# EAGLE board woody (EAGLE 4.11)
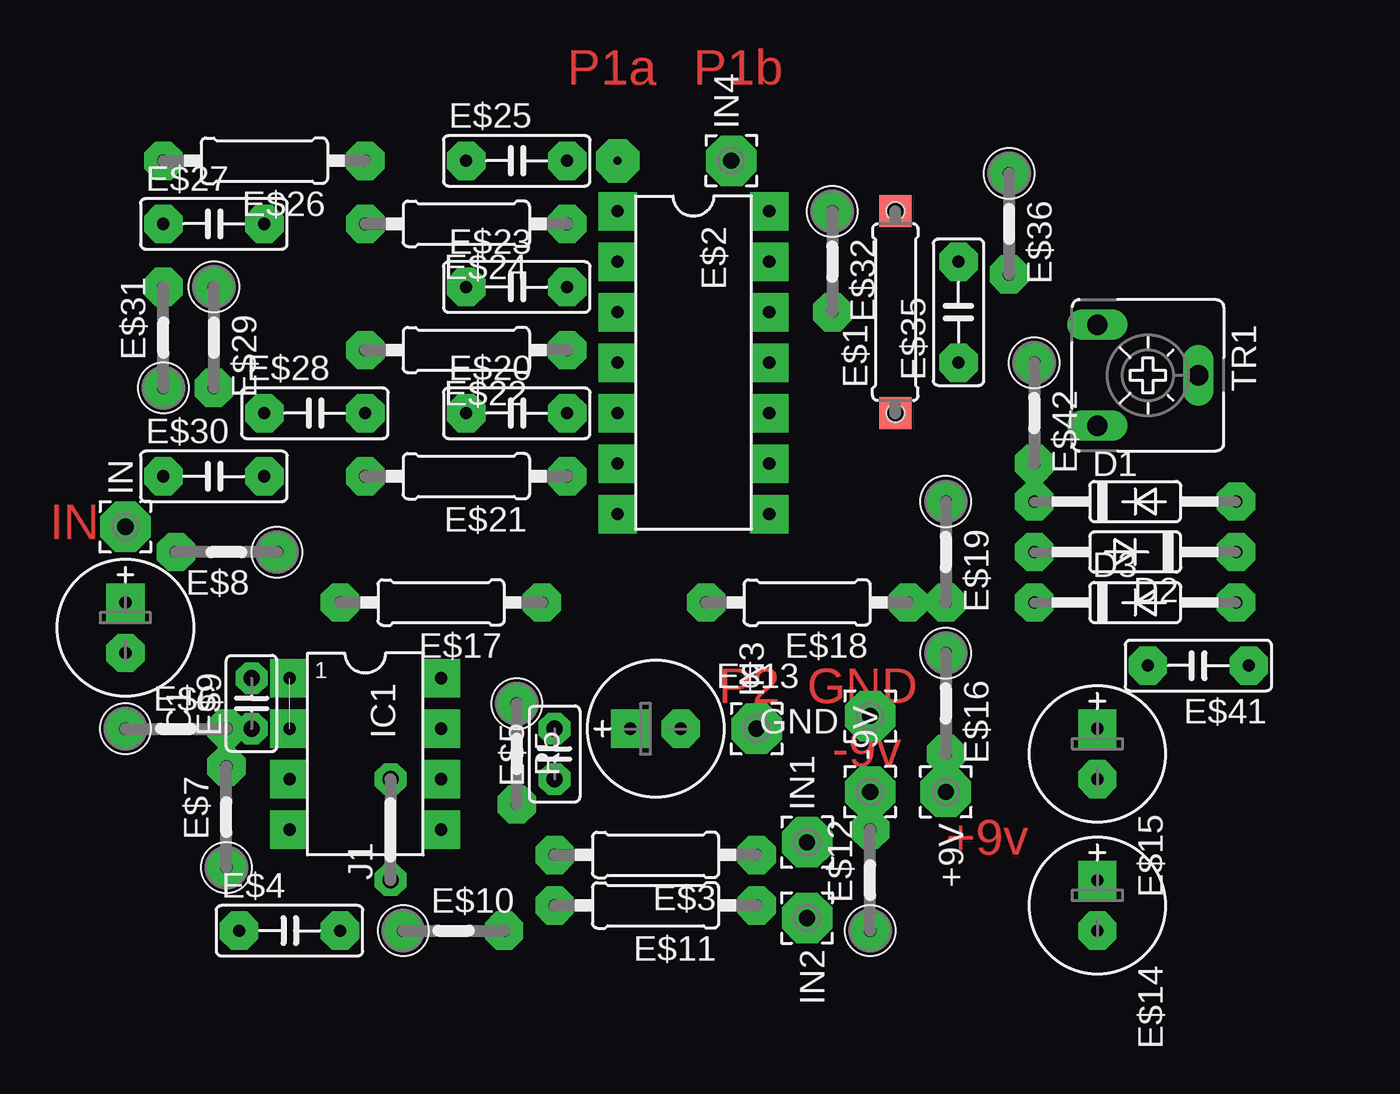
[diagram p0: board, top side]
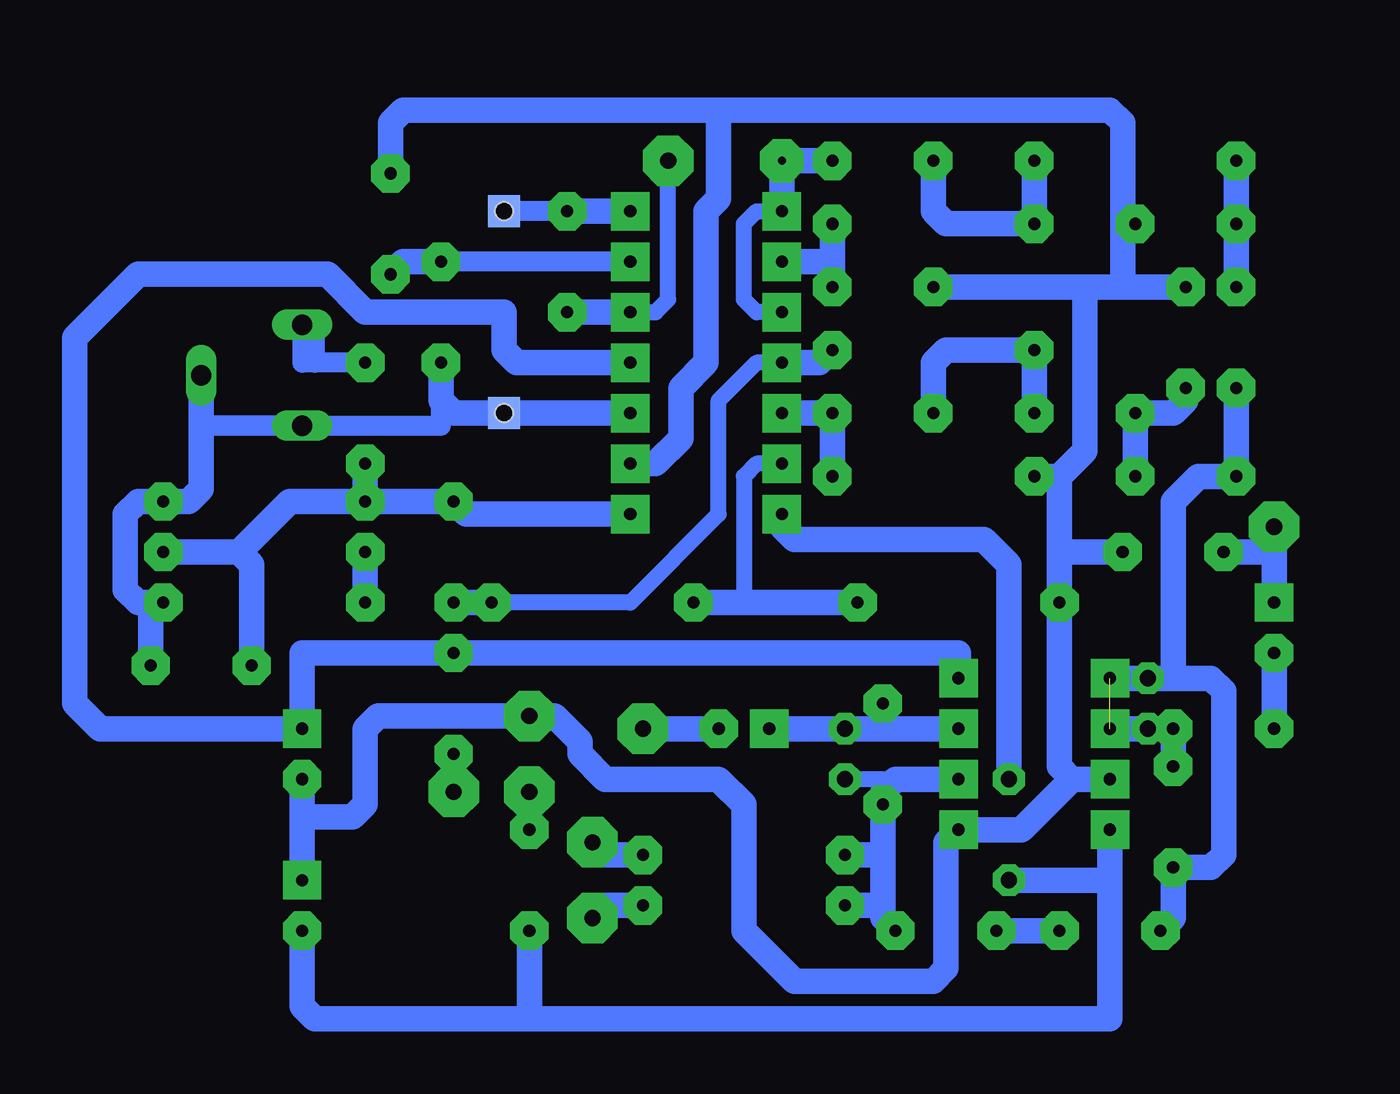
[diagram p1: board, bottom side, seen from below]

No outline drawn. Coordinates in mm, seen from the top.
Copper layers (1*16): Top 0.035mm / dielectric 1.5mm / Bottom 0.035mm
Design rules "default": minimum track width 10mil, minimum drill 24mil, track to track 8mil, track to pad 8mil, pad to pad 8mil, via to via 8mil, smd to smd 8mil, copper to edge 40mil, drill to drill 8mil, minimum pad ring 10mil, minimum via ring 8mil, stop-mask expansion 4mil, vias tented up to drill 0mil, thermal gap 10mil

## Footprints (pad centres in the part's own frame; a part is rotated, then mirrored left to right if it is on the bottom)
2,54/0,8 = drill 0.813 pad 2.54 octagon: 1 0,0
E2,5-7 = drill 0.61 pad 1.93 square: + -1.27,0 | drill 0.61 pad 1.93 octagon: - 1.27,0
DO35-10 = drill 0.61 pad 1.93 octagon: A 5.08,0; C -5.08,0
R4207/10 = smd 1.6 x 1.6: A1 -5.08,0; A2 5.08,0 | smd 1.6 x 1.6 bottom: B1 -5.08,0; B2 5.08,0 | hole 0.9: -5.08,0; 5.08,0
DIL14 = drill 0.61 pad 1.93 square: 1 -7.62,-3.81; 2 -5.08,-3.81; 3 -2.54,-3.81; 4 0,-3.81; 5 2.54,-3.81; 6 5.08,-3.81; 7 7.62,-3.81; 8 7.62,3.81; 9 5.08,3.81; 10 2.54,3.81; 11 0,3.81; 12 -2.54,3.81; 13 -5.08,3.81; 14 -7.62,3.81
0207/10 = drill 0.61 pad 1.93 octagon: 1 -5.08,0; 2 5.08,0
C050-025X075 = drill 0.61 pad 1.93 octagon: 1 -2.54,0; 2 2.54,0
C2.5-2 = drill 0.813 pad 1.6 octagon: 1 -1.27,0; 2 1.27,0
0207/5V = drill 0.61 pad 1.93 octagon: 1 -2.54,0; 2 2.54,0
DIL08 = drill 0.61 pad 1.93 square: 1 -3.81,-3.81; 2 -1.27,-3.81; 3 1.27,-3.81; 4 3.81,-3.81; 5 3.81,3.81; 6 1.27,3.81; 7 -1.27,3.81; 8 -3.81,3.81
05 = drill 0.813 pad 1.6 octagon: 1 -2.54,0; 2 2.54,0
CA6V = drill 1.016 long: A -2.54,-2.54; E 2.54,-2.54; S 0,2.54

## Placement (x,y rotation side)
+9V  [2,54/0,8]  48.9,17.14 180 top
-9V  [2,54/0,8]  45.09,17.14 0 top
C1  1uf  [E2,5-7]  7.62,25.4 270 top
D1  1N4148  [DO35-10]  58.42,31.75 0 top
D2  1N4148  [DO35-10]  58.42,29.21 180 top
D3  1N4148  [DO35-10]  58.42,26.67 0 top
E$1  10K  [R4207/10]  46.35,41.27 90 top
E$2  LM4136  [DIL14]  36.2,38.73 270 top
E$3  3K3  [0207/10]  34.29,13.97 180 top
E$4  39nf  [C050-025X075]  15.88,10.16 0 top
E$5  small pf cap  [C2.5-2]  29.21,19.05 90 top
E$6  10K  [0207/5V]  10.16,20.32 0 top
E$7  12K  [0207/5V]  12.7,15.88 90 top
E$8  1M  [0207/5V]  12.7,29.21 180 top
E$9  small pf cap  [C2.5-2]  13.97,21.59 90 top
E$10  12K  [0207/5V]  24.13,10.16 0 top
E$11  12K  [0207/10]  34.29,11.43 180 top
E$12  100  [0207/5V]  45.09,12.7 90 top
E$13  10uf  [E2,5-7]  34.29,20.32 0 top
E$14  47uf  [E2,5-7]  56.52,11.43 270 top
E$15  47uf  [E2,5-7]  56.52,19.05 270 top
E$16  100  [0207/5V]  48.9,21.59 270 top
E$17  22K  [0207/10]  23.5,26.67 180 top
E$18  22K  [0207/10]  41.91,26.67 180 top
E$19  10K  [0207/5V]  48.9,29.21 270 top
E$20  3n3  [C050-025X075]  27.3,36.2 0 top
E$21  10K  [0207/10]  24.77,33.02 180 top
E$22  10K  [0207/10]  24.77,39.37 180 top
E$23  39nf  [C050-025X075]  27.3,42.55 0 top
E$24  10K  [0207/10]  24.77,45.72 180 top
E$25  39nf  [C050-025X075]  27.3,48.9 0 top
E$26  10K  [0207/10]  14.61,48.9 180 top
E$27  39nf  [C050-025X075]  12.06,45.72 0 top
E$28  3n3  [C050-025X075]  17.14,36.2 0 top
E$29  10k  [0207/5V]  12.06,40.01 270 top
E$30  3n3  [C050-025X075]  12.06,33.02 0 top
E$31  10k  [0207/5V]  9.53,40.01 90 top
E$32  10K  [0207/5V]  43.18,43.81 270 top
E$35  10nf  [C050-025X075]  49.53,41.27 90 top
E$36  100K  [0207/5V]  52.07,45.72 270 top
E$41  100pf  [C050-025X075]  61.59,23.5 180 top
E$42  150K  [0207/5V]  53.34,36.2 270 top
GND  [2,54/0,8]  45.09,20.95 90 top
IC1  TL072  [DIL08]  19.68,19.05 270 top
IN  [2,54/0,8]  7.62,30.48 0 top
IN1  [2,54/0,8]  41.91,14.61 0 top
IN2  [2,54/0,8]  41.91,10.79 180 top
IN3  OUT  [2,54/0,8]  39.37,20.32 0 top
IN4  [2,54/0,8]  38.1,48.9 0 top
J1  0K  [05]  20.95,15.24 90 top
R5  22K  [0207/5V]  27.3,19.05 270 top
TR1  500K  [CA6V]  59.05,38.1 270 top

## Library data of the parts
+9V -9V GND IN IN1-IN4 = wirepad
C1 E$3 E$4 E$6-E$8 E$10-E$32 E$35 E$36 E$41 E$42 R5 = rcl
D1-D3 = diode
E$1 = resistor-ruf
E$2 IC1 = ic-package
E$5 E$9 = capacitor-wima
J1 = jumper
TR1 = pot

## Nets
IC2: E$2.9 E$8.1 E$14.+ E$15.- E$17.2 E$21.2 E$23.1 E$27.2 E$29.1 E$36.1 GND.1 IC1.3 IC1.5
R2: E$4.1 E$6.2 E$7.1 E$7.2 E$30.1 E$31.1 IC1.1 IC1.2
S$1: C1.+ E$8.2 IN.1
S$2: C1.- E$6.1
S$4: D1.A D3.A E$2.10 E$35.1 E$41.1 TR1.E TR1.S
S$5: E$13.- IN3.1
S$6: E$11.1 IN2.1
S$7: E$2.7 J1.2
S$8: E$3.2 E$10.2 E$11.2 IC1.6 R5.2
S$9: E$13.+ IC1.7 R5.1
S$10: E$4.2 E$10.1
S$11: E$3.1 IN1.1
S$12: -9V.1 E$12.2
S$13: E$2.11 E$15.+ E$16.1 IC1.8
S$14: E$2.6 E$17.1 E$18.2
S$15: +9V.1 E$16.2
S$16: E$42.1 TR1.A
S$17: E$2.4 E$18.1 E$19.2 E$22.1
S$18: E$5.1
S$20: E$2.5 E$20.2 E$21.1
S$21: E$20.1 E$22.2 E$28.2
S$22: E$2.2 E$23.2 E$24.1
S$23: E$2.1 E$2.3 E$25.2
S$24: E$24.2 E$25.1 E$26.1
S$25: E$26.2 E$27.1 E$31.2
S$26: E$28.1 E$29.2 E$30.2
S$32: E$2.12 E$32.2 IN4.1
S$33: E$1.A2 E$2.14 E$32.1
S$36: E$2.13 E$35.2 E$36.2
S$37: D2.A D3.C
S$38: D1.C D2.C E$2.8 E$19.1 E$41.2 E$42.2
V-: E$12.1 E$14.- IC1.4 J1.1

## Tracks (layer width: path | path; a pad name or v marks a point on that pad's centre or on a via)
IC2
  Bottom 1.27: E$2.9 38.73,33.66 37.47,34.92 37.47,37.47 36.2,38.73 36.2,46.35 35.56,46.99 35.56,51.44 | E$36.1 52.07,50.8 51.44,51.44 35.56,51.44 | 56.52,15.88 E$14.+ | 56.52,15.88 E$15.- | 56.52,15.88 53.98,15.88 53.34,16.51 53.34,20.32 52.7,20.95 GND.1 43.81,20.95 42.55,19.68 42.55,19.05 41.27,17.78 35.56,17.78 34.29,16.51 34.29,10.16 31.75,7.62 24.77,7.62 24.13,8.26 24.13,14.61 IC1.5 20.32,15.24 17.78,17.78 | 35.56,51.44 15.88,51.44 15.24,50.8 15.24,42.55 | E$27.2 15.24,45.72 15.24,42.55 | 15.24,42.55 E$29.1 | 17.14,42.55 E$23.1 | 17.14,42.55 15.24,42.55 | 17.14,42.55 17.14,34.29 18.41,33.02 | 18.41,33.02 E$21.2 | 18.41,29.21 E$8.1 | 18.41,29.21 18.41,33.02 | 18.41,29.21 E$17.2 18.41,18.41 17.78,17.78 | 17.78,17.78 IC1.3
R2  (1 unrouted)
  Bottom 1.27: 12.7,22.86 10.79,22.86 10.16,22.23 10.16,13.97 10.79,13.34 E$7.1 12.7,10.79 E$4.1 | 12.7,22.86 IC1.1 | 12.7,22.86 12.7,31.75 11.43,33.02 E$30.1 E$31.1 | IC1.2 E$6.2 E$7.2
S$1
  Bottom 1.27: IN.1 7.62,29.21 | 7.62,29.21 C1.+ | E$8.2 7.62,29.21
S$2
  Bottom 1.27: C1.- E$6.1
S$3  (via drill 0.41 pad 2.18)
  other vias: 32.38,48.9
S$4
  Bottom 1.016: TR1.E 61.59,35.56 49.53,35.56 49.53,36.83
  Bottom 1.27: TR1.S 61.59,35.56 61.59,32.38 62.23,31.75 D1.A 64.77,31.75 65.41,31.11 65.41,27.3 64.77,26.67 64.14,26.67 | 64.14,26.67 D3.A | E$41.1 64.14,26.67 | E$35.1 49.53,36.83 48.9,36.2 E$2.10
S$5
  Bottom 1.27: E$13.- IN3.1
S$6
  Bottom 1.27: E$11.1 41.27,11.43 | 41.27,11.43 IN2.1 | 41.27,11.43 IN2.1 | 41.27,11.43 IN2.1
S$7
  Bottom 1.27: E$2.7 32.38,30.48 31.75,29.84 22.23,29.84 20.95,28.57 J1.2
S$8
  Bottom 1.27: IC1.6 26.67,17.78 27.3,17.14 R5.2 27.3,13.97 | 27.3,13.97 27.3,11.43 | 27.3,11.43 27.3,10.79 E$10.2 | E$11.2 27.3,11.43 | E$3.2 27.3,13.97
S$9
  Bottom 1.27: IC1.7 27.3,20.32 | 27.3,20.32 R5.1 | 27.3,20.32 E$13.+
S$10
  Bottom 1.27: E$4.2 E$10.1
S$11
  Bottom 1.27: E$3.1 41.27,13.97 | 41.27,13.97 IN1.1 41.27,13.97
S$12
  Bottom 1.27: -9V.1 E$12.2
S$13
  Bottom 1.27: IC1.8 23.5,24.13 E$16.1 56.52,24.13 E$15.+ 66.67,20.32 67.94,21.59 67.94,40.01 64.77,43.18 55.24,43.18 53.34,41.27 46.35,41.27 46.35,39.37 45.72,38.73 E$2.11
S$14
  Bottom 0.813: E$2.6 33.66,33.66 34.29,33.02 34.29,26.67
  Bottom 1.27: E$17.1 34.29,26.67 E$18.2
S$15
  Bottom 1.27: E$16.2 +9V.1
S$16
  Bottom 1.016: E$42.1 55.88,38.73 | 55.88,38.73 56.52,38.73 TR1.A | 55.88,40.64 55.88,38.73
S$17
  Bottom 0.813: E$18.1 40.01,26.67 35.56,31.11 35.56,36.83 33.66,38.73 E$2.4
  Bottom 1.27: E$18.1 E$19.2 | E$2.4 30.48,38.73 E$22.1
S$18
  Bottom 0.813: 27.3,17.78 E$5.1
S$20
  Bottom 1.27: E$2.5 E$20.2 E$21.1
S$21
  Bottom 1.27: E$20.1 24.77,38.73 24.13,39.37 E$22.2 E$28.2
S$22
  Bottom 1.27: E$2.2 29.84,43.81 | E$23.2 29.84,43.81 | 29.84,43.81 E$24.1
S$23
  Bottom 0.813: E$2.3 33.66,41.27 34.29,41.91 34.29,45.72 33.66,46.35 E$2.1
  Bottom 1.27: E$25.2 31.75,48.9 32.38,48.26 E$2.1
S$24
  Bottom 1.27: E$25.1 24.77,46.35 24.13,45.72 E$24.2 E$26.1
S$25
  Bottom 1.27: E$26.2 E$27.1 E$31.2
S$26
  Bottom 1.27: E$29.2 12.06,36.83 12.7,36.2 E$28.1 E$30.2
S$32
  Bottom 0.813: E$2.12 38.73,41.27 38.1,41.91 IN4.1
  Bottom 1.27: E$32.2 E$2.12
S$33
  Bottom 1.016: E$32.1 E$1.A2
  Bottom 1.27: E$2.14 E$32.1
S$36
  Bottom 1.016: E$2.13 E$35.2
  Bottom 1.27: E$36.2 51.44,43.81 E$35.2
S$37
  Bottom 1.27: D3.C D2.A
S$38
  Bottom 1.27: D1.C 57.15,31.75 59.69,29.21 | 59.69,29.21 D2.C | E$41.2 59.05,28.57 59.69,29.21 | E$2.8 48.26,31.11 E$19.1 D1.C | D1.C E$42.2
V-
  Bottom 1.27: IC1.4 15.88,12.7 | 15.88,12.7 15.88,5.71 45.09,5.71 | E$12.1 45.09,5.71 | 45.09,5.71 55.88,5.71 56.52,6.35 E$14.- | J1.1 15.88,12.7

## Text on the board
Top: P1a | P1b | IN | P2 | GND | -9v | +9v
